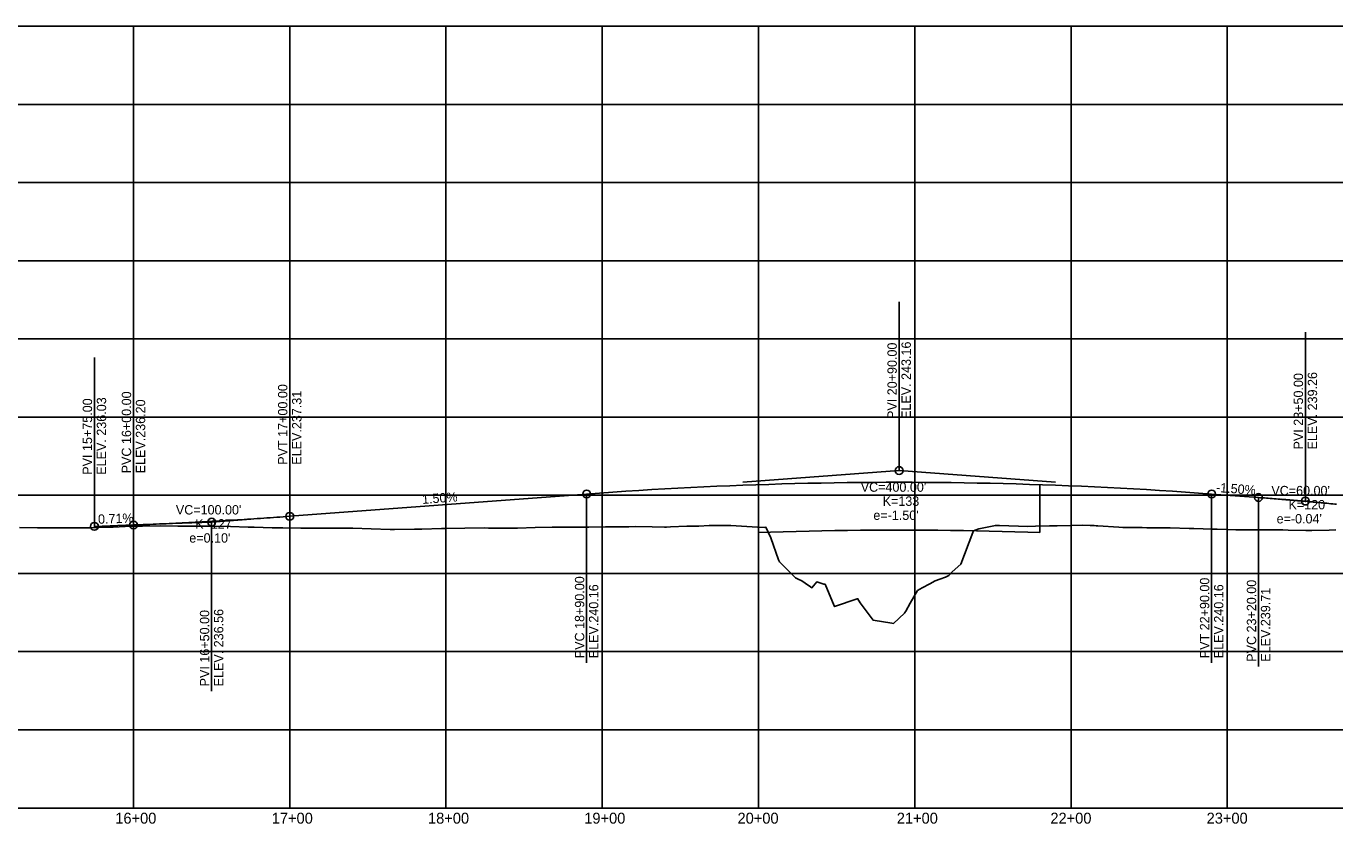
# Model space of a CAD drawing. Extents: x 976639 to 985448, y 1524031 to 1526806.
# Drawn here: x 977841 to 978678, y 1524043 to 1524553 of the extents above; entities that cross this region are included whole.
import ezdxf

# ---------------------------------------------------------------- set-up
doc = ezdxf.new("R2010")
doc.units = 0
for name, color, linetype in [('B_Concrete', 7, 'Continuous'), ('Default', 7, 'Continuous'), ('R_Axis', 7, 'Continuous'), ('R_Axis Annot', 7, 'Continuous'), ('R_Grid', 7, 'Continuous'), ('R_Vert Alg', 7, 'Continuous'), ('R_Vert Alg Annot', 7, 'Continuous'), ('S_WORKING_LINES', 7, 'Continuous')]:
    doc.layers.add(name, color=color, linetype=linetype)

msp = doc.modelspace()

# ---------------------------------------------------------------- linework, layer by layer
at = {"layer": 'B_Concrete'}
for p, q in [((978309.31, 1524229.71), (978309.31, 1524260.27)), ((978489.31, 1524260.27), (978489.31, 1524229.71))]:
    msp.add_line(p, q, dxfattribs=at)
msp.add_lwpolyline([(978309.31, 1524229.71), (978316.93, 1524229.96), (978325.17, 1524230.2), (978333.41, 1524230.42), (978341.64, 1524230.61), (978349.88, 1524230.78), (978358.12, 1524230.92), (978366.36, 1524231.04), (978374.6, 1524231.13), (978382.83, 1524231.19), (978391.05, 1524231.23), (978407.57, 1524231.23), (978415.78, 1524231.19), (978424.02, 1524231.13), (978432.26, 1524231.04), (978440.5, 1524230.92), (978448.74, 1524230.78), (978456.97, 1524230.61), (978465.21, 1524230.42), (978473.45, 1524230.2), (978481.69, 1524229.96), (978489.31, 1524229.71)], dxfattribs=at)
at = {"layer": 'Default'}
msp.add_lwpolyline([(977836.31, 1524232.94), (977847.88, 1524232.64), (977851.31, 1524232.66), (977862.81, 1524232.66), (977866.31, 1524232.68), (977877.94, 1524232.67), (977881.35, 1524232.71), (977892.85, 1524233.05), (977896.35, 1524233.08), (977907.8, 1524233.64), (977911.35, 1524233.66), (977914.98, 1524233.68), (977926.35, 1524233.87), (977937.6, 1524233.85), (977941.35, 1524233.83), (977945.13, 1524233.8), (977956.35, 1524233.69), (977960.24, 1524233.65), (977971.48, 1524233.55), (977982.8, 1524233.05), (977986.48, 1524233.03), (977998.02, 1524232.66), (978001.48, 1524232.64), (978004.89, 1524232.59), (978016.48, 1524232.43), (978019.77, 1524232.37), (978031.48, 1524232.52), (978034.66, 1524232.48), (978046.48, 1524232.45), (978049.59, 1524232.39), (978061.45, 1524232.1), (978073.55, 1524231.59), (978076.45, 1524231.54), (978089.07, 1524231.8), (978091.45, 1524231.77), (978093.82, 1524231.78), (978106.45, 1524232.18), (978108.89, 1524232.15), (978121.45, 1524232.48), (978133.66, 1524232.62), (978136.45, 1524232.57), (978139.19, 1524232.54), (978151.45, 1524232.53), (978154.98, 1524232.51), (978166.45, 1524232.95), (978177.26, 1524233.11), (978181.31, 1524233.09), (978185.41, 1524233.17), (978196.31, 1524233.11), (978200.7, 1524233.16), (978211.31, 1524233.29), (978221.81, 1524233.36), (978226.31, 1524233.37), (978230.85, 1524233.43), (978241.31, 1524233.27), (978249.17, 1524233.13), (978250.37, 1524233.18), (978253.03, 1524233.34), (978263.47, 1524233.78), (978271.19, 1524233.83), (978277.63, 1524234.1), (978286.22, 1524234.13), (978291.53, 1524234.18), (978308.63, 1524233.02), (978312.98, 1524232.98), (978314.06, 1524233.04), (978317.18, 1524226.22), (978322.14, 1524212.31), (978322.84, 1524210.83), (978332.31, 1524201.34), (978332.99, 1524200.79), (978334.79, 1524199.95), (978336.94, 1524198.86), (978339.18, 1524197.36), (978342.68, 1524194.89), (978343.49, 1524194.39), (978346.58, 1524198.06), (978346.74, 1524198.21), (978351.16, 1524196.68), (978351.97, 1524196.74), (978357.78, 1524182.74), (978358.01, 1524182.35), (978372.5, 1524187.36), (978372.74, 1524187.43), (978374.45, 1524184.73), (978382.62, 1524173.64), (978394.6, 1524171.66), (978395.66, 1524171.51), (978402.64, 1524178.17), (978403.02, 1524178.46), (978403.53, 1524179.45), (978406.44, 1524184.52), (978410.98, 1524192.53), (978414.03, 1524194.31), (978418.91, 1524196.91), (978422.27, 1524198.72), (978425.39, 1524199.83), (978428.9, 1524201.14), (978431.16, 1524202.12), (978431.21, 1524202.13), (978433.16, 1524204.61), (978438.75, 1524209.41), (978438.76, 1524209.4), (978446.41, 1524229.73), (978446.81, 1524230.8), (978450.37, 1524232.03), (978460.93, 1524234.27), (978463.63, 1524234.26), (978481.7, 1524233.62), (978486.5, 1524233.76), (978495.44, 1524233.97), (978500.41, 1524234), (978509.24, 1524234.2), (978516.96, 1524234.42), (978521.55, 1524234.24), (978524.12, 1524234.2), (978525.39, 1524234.03), (978526.54, 1524234), (978539.86, 1524233.06), (978542.57, 1524232.99), (978554.77, 1524232.79), (978557.74, 1524232.73), (978569.74, 1524232.64), (978572.8, 1524232.61), (978584.9, 1524232.34), (978587.88, 1524232.29), (978599.96, 1524231.87), (978602.82, 1524231.82), (978614.83, 1524231.5), (978618.05, 1524231.46), (978629.77, 1524231.45), (978633.17, 1524231.42), (978644.78, 1524231.3), (978648.18, 1524231.27), (978659.61, 1524230.98), (978663.5, 1524230.99), (978674.44, 1524231.28), (978678.71, 1524231.3)], dxfattribs=at)
at = {"layer": 'R_Axis'}
msp.add_line((977009.31, 1524053.49), (979809.31, 1524053.49), dxfattribs=at)
at = {"layer": 'R_Grid'}
for p, q in [((977009.31, 1524553.49), (979809.31, 1524553.49)), ((977009.31, 1524553.49), (979809.31, 1524553.49)), ((977909.31, 1524053.49), (977909.31, 1524553.49)), ((978009.31, 1524053.49), (978009.31, 1524553.49)), ((978109.31, 1524053.49), (978109.31, 1524553.49)), ((978209.31, 1524053.49), (978209.31, 1524553.49)), ((978309.31, 1524053.49), (978309.31, 1524553.49)), ((978409.31, 1524053.49), (978409.31, 1524553.49)), ((978509.31, 1524053.49), (978509.31, 1524553.49)), ((978609.31, 1524053.49), (978609.31, 1524553.49)), ((977009.31, 1524503.49), (979809.31, 1524503.49)), ((977009.31, 1524453.49), (979809.31, 1524453.49)), ((977009.31, 1524403.49), (979809.31, 1524403.49)), ((977009.31, 1524353.49), (979809.31, 1524353.49)), ((977009.31, 1524303.49), (979809.31, 1524303.49)), ((977009.31, 1524253.49), (979809.31, 1524253.49)), ((977009.31, 1524203.49), (979809.31, 1524203.49)), ((977009.31, 1524153.49), (979809.31, 1524153.49)), ((977009.31, 1524103.49), (979809.31, 1524103.49))]:
    msp.add_line(p, q, dxfattribs=at)
at = {"layer": 'R_Vert Alg'}
for p, q in [((978299.31, 1524261.79), (978399.31, 1524269.29)), ((978399.31, 1524269.29), (978499.31, 1524261.79)), ((978009.31, 1524240.04), (978199.31, 1524254.29)), ((978599.31, 1524254.29), (978629.31, 1524252.04)), ((978644.31, 1524250.92), (978659.31, 1524249.79)), ((978659.31, 1524249.79), (978674.31, 1524248.29)), ((977884.31, 1524233.63), (977909.31, 1524234.52)), ((977934.31, 1524235.4), (977959.31, 1524236.29)), ((977959.31, 1524236.29), (977984.31, 1524238.17))]:
    msp.add_line(p, q, dxfattribs=at)
for points in [[(978199.31, 1524254.29), (978207.64, 1524254.9), (978215.98, 1524255.49), (978224.31, 1524256.05), (978232.64, 1524256.58), (978240.98, 1524257.09), (978249.31, 1524257.57), (978257.64, 1524258.03), (978265.98, 1524258.46), (978274.31, 1524258.86), (978282.64, 1524259.24), (978290.98, 1524259.59), (978299.31, 1524259.92), (978307.64, 1524260.22), (978315.98, 1524260.49), (978324.31, 1524260.74), (978332.64, 1524260.96), (978340.98, 1524261.15), (978349.31, 1524261.32), (978357.64, 1524261.47), (978365.98, 1524261.58), (978374.31, 1524261.68), (978382.64, 1524261.74), (978390.98, 1524261.78), (978407.64, 1524261.78), (978415.98, 1524261.74), (978424.31, 1524261.68), (978432.64, 1524261.58), (978440.98, 1524261.47), (978449.31, 1524261.32), (978457.64, 1524261.15), (978465.98, 1524260.96), (978474.31, 1524260.74), (978482.64, 1524260.49), (978490.98, 1524260.22), (978499.31, 1524259.92), (978507.64, 1524259.59), (978515.98, 1524259.24), (978524.31, 1524258.86), (978532.64, 1524258.46), (978540.98, 1524258.03), (978549.31, 1524257.57), (978557.64, 1524257.09), (978565.98, 1524256.58), (978574.31, 1524256.05), (978582.64, 1524255.49), (978590.98, 1524254.9), (978599.31, 1524254.29)], [(978629.31, 1524252.04), (978630.56, 1524251.95), (978631.81, 1524251.85), (978633.06, 1524251.76), (978634.31, 1524251.66), (978635.56, 1524251.57), (978636.81, 1524251.47), (978638.06, 1524251.37), (978639.31, 1524251.27), (978640.56, 1524251.17), (978641.81, 1524251.07), (978643.06, 1524250.97), (978644.31, 1524250.87), (978645.56, 1524250.77), (978646.81, 1524250.67), (978648.06, 1524250.56), (978649.31, 1524250.46), (978650.56, 1524250.35), (978651.81, 1524250.25), (978653.06, 1524250.14), (978654.31, 1524250.04), (978655.56, 1524249.93), (978656.81, 1524249.82), (978658.06, 1524249.71), (978660.56, 1524249.5), (978661.81, 1524249.39), (978663.06, 1524249.27), (978664.31, 1524249.16), (978665.56, 1524249.05), (978666.81, 1524248.94), (978668.06, 1524248.82), (978669.31, 1524248.71), (978670.56, 1524248.59), (978671.81, 1524248.48), (978673.06, 1524248.36), (978674.31, 1524248.25), (978675.56, 1524248.13), (978676.81, 1524248.01), (978678.06, 1524247.89), (978679.31, 1524247.77)], [(977909.31, 1524234.52), (977911.39, 1524234.59), (977913.48, 1524234.67), (977915.56, 1524234.75), (977917.64, 1524234.83), (977919.73, 1524234.91), (977921.81, 1524234.99), (977923.89, 1524235.08), (977925.98, 1524235.16), (977928.06, 1524235.25), (977930.14, 1524235.34), (977932.23, 1524235.43), (977934.31, 1524235.53), (977936.39, 1524235.62), (977938.48, 1524235.72), (977940.56, 1524235.82), (977942.64, 1524235.92), (977944.73, 1524236.02), (977946.81, 1524236.13), (977948.89, 1524236.23), (977950.98, 1524236.34), (977953.06, 1524236.45), (977955.14, 1524236.56), (977957.23, 1524236.67), (977961.39, 1524236.9), (977963.48, 1524237.02), (977965.56, 1524237.14), (977967.64, 1524237.26), (977969.73, 1524237.38), (977971.81, 1524237.51), (977973.89, 1524237.63), (977975.98, 1524237.76), (977978.06, 1524237.89), (977980.14, 1524238.02), (977982.23, 1524238.16), (977984.31, 1524238.29), (977986.39, 1524238.43), (977988.48, 1524238.57), (977990.56, 1524238.71), (977992.64, 1524238.85), (977994.73, 1524238.99), (977996.81, 1524239.14), (977998.89, 1524239.28), (978000.98, 1524239.43), (978003.06, 1524239.58), (978005.14, 1524239.73), (978007.23, 1524239.89), (978009.31, 1524240.04)]]:
    msp.add_lwpolyline(points, dxfattribs=at)
at = {"layer": 'R_Vert Alg Annot'}
for p, q in [((978399.31, 1524299.29), (978399.31, 1524377.29)), ((978659.31, 1524279.79), (978659.31, 1524357.79)), ((978009.31, 1524270.04), (978009.31, 1524348.04)), ((977884.31, 1524263.63), (977884.31, 1524341.63)), ((977909.31, 1524264.52), (977909.31, 1524342.52)), ((978399.31, 1524269.29), (978399.31, 1524299.29)), ((978659.31, 1524249.79), (978659.31, 1524279.79)), ((977884.31, 1524233.63), (977884.31, 1524263.63)), ((977909.31, 1524234.52), (977909.31, 1524264.52)), ((978009.31, 1524240.04), (978009.31, 1524270.04)), ((978199.31, 1524254.29), (978199.31, 1524224.29)), ((978599.31, 1524254.29), (978599.31, 1524224.29)), ((978629.31, 1524252.04), (978629.31, 1524222.04)), ((977959.31, 1524236.29), (977959.31, 1524206.29)), ((978199.31, 1524224.29), (978199.31, 1524146.29)), ((978599.31, 1524224.29), (978599.31, 1524146.29)), ((978629.31, 1524222.04), (978629.31, 1524144.04)), ((977959.31, 1524206.29), (977959.31, 1524128.29))]:
    msp.add_line(p, q, dxfattribs=at)
for centre in [(978399.31, 1524269.29), (978199.31, 1524254.29), (978599.31, 1524254.29), (978629.31, 1524252.04), (978659.31, 1524249.79), (977959.31, 1524236.29), (978009.31, 1524240.04), (977884.31, 1524233.63), (977909.31, 1524234.52)]:
    msp.add_circle(centre, 2.5, dxfattribs=at)
at = {"layer": 'S_WORKING_LINES'}
msp.add_line((977884.31, 1524232.8), (977884.31, 1524233.63), dxfattribs=at)

# ---------------------------------------------------------------- texts
at = {"layer": 'R_Axis Annot'}
for s, p in [('16+00', (977897.66, 1524043.49)), ('17+00', (977997.8, 1524043.49)), ('18+00', (978097.8, 1524043.49)), ('19+00', (978197.8, 1524043.49)), ('20+00', (978295.87, 1524043.49)), ('21+00', (978397.8, 1524043.49)), ('22+00', (978496.1, 1524043.49)), ('23+00', (978596.1, 1524043.49))]:
    msp.add_text(s, height=7, dxfattribs=at).set_placement(p)
at = {"layer": 'R_Vert Alg Annot'}
for s, rotation, p in [('PVI 20+90.00', 90, (978397.81, 1524302.29)), ('ELEV. 243.16', 90, (978406.81, 1524302.29)), ('PVI 23+50.00', 90, (978657.81, 1524282.79)), ('ELEV. 239.26', 90, (978666.81, 1524282.79)), ('PVT 17+00.00', 90, (978007.81, 1524273.04)), ('PVI 15+75.00', 90, (977882.81, 1524266.63)), ('ELEV. 236.03', 90, (977891.81, 1524266.63)), ('PVC 16+00.00', 90, (977907.81, 1524267.52)), ('ELEV.236.20', 90, (977916.81, 1524267.52)), ('ELEV.237.31', 90, (978016.81, 1524273.04)), ('1.50%', 4.28915, (978094.19, 1524247.91)), ('-1.50%', 355.71085, (978601.96, 1524255.6)), ('0.71%', 2.03357, (977886.72, 1524235.22)), ('PVC 18+90.00', 90, (978197.81, 1524149.29)), ('PVT 22+90.00', 90, (978597.81, 1524149.29)), ('PVC 23+20.00', 90, (978627.81, 1524147.04)), ('ELEV.240.16', 90, (978206.81, 1524149.29)), ('ELEV.240.16', 90, (978606.81, 1524149.29)), ('ELEV.239.71', 90, (978636.81, 1524147.04)), ('PVI 16+50.00', 90, (977957.81, 1524131.29)), ('ELEV. 236.56', 90, (977966.81, 1524131.29))]:
    msp.add_text(s, height=6, rotation=rotation, dxfattribs=at).set_placement(p)
for s, p in [("VC=400.00'", (978374.74, 1524255.74)), ("VC=60.00'", (978637.53, 1524253.49)), ("VC=100.00'", (977936.44, 1524241.22)), ('K=133', (978388.77, 1524246.74)), ('K=120', (978648.51, 1524244.49)), ('K=127', (977948.77, 1524232.22)), ("e=-1.50'", (978382.82, 1524237.74)), ("e=-0.04'", (978640.88, 1524235.49)), ("e=0.10'", (977945.04, 1524223.22))]:
    msp.add_text(s, height=6, dxfattribs=at).set_placement(p)

doc.saveas('drawing.dxf')
